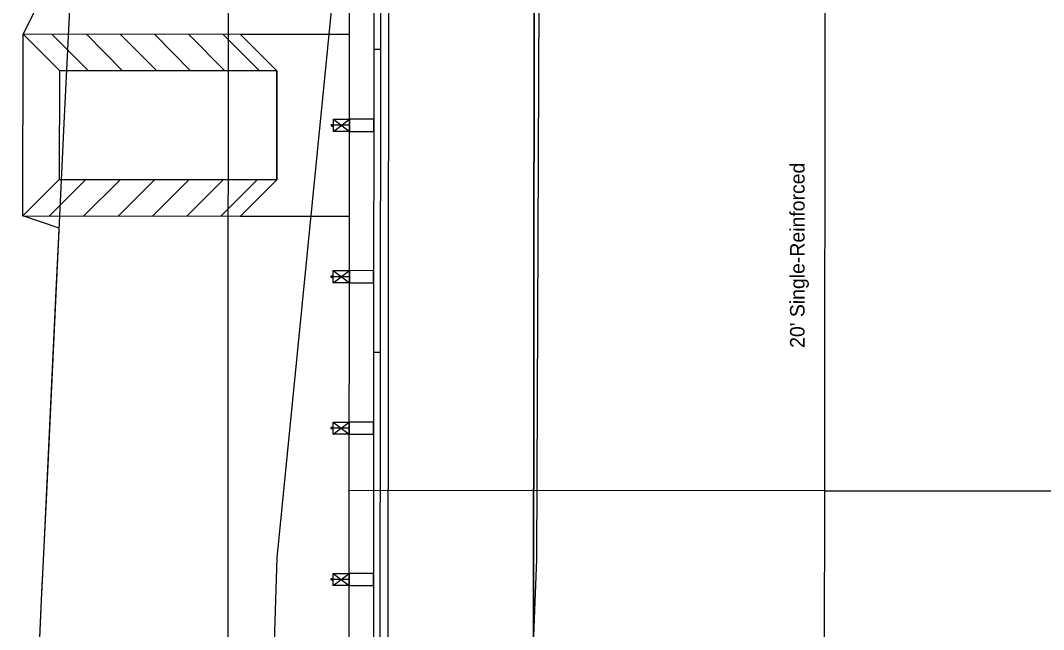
# Model space of a CAD drawing. Extents: x 18543285 to 18543485, y 7434209 to 7435438.
# Drawn here: x 18543351.49 to 18543393.73, y 7434698.69 to 7434723.84 of the extents above; entities that cross this region are included whole.
import ezdxf

# ---------------------------------------------------------------- set-up
doc = ezdxf.new("R2010")
doc.units = 0
for name, color, linetype in [('_CIVIL_CONSTRUCTION', 7, 'Continuous'), ('Contours Major', 7, 'Continuous'), ('Dimensions', 7, 'Continuous'), ('Draft_1', 7, 'Continuous'), ('EdgeUnpaved', 7, 'Continuous'), ('EXT_SNP', 7, 'Continuous'), ('MeshTop', 7, 'Continuous'), ('Terrain', 7, 'Continuous'), ('TL_ForeSlope', 7, 'Continuous'), ('TL_Grading', 7, 'Continuous'), ('TL_GroundIntercept', 7, 'Continuous')]:
    doc.layers.add(name, color=color, linetype=linetype)

# ---------------------------------------------------------------- blocks, each defined once
blk = doc.blocks.new('MGS_Barrier_Transition_TypeD')
at = {"layer": 'TL_Grading'}
for p, q in [((24.167, -0.25), (36.667, -0.25)), ((36.667, -0.52), (36.667, -0.25)), ((24.167, -0.52), (36.667, -0.52))]:
    blk.add_line(p, q, dxfattribs=at)

msp = doc.modelspace()

# ---------------------------------------------------------------- linework, layer by layer
at = {"layer": '_CIVIL_CONSTRUCTION'}
msp.add_line((18543372.717, 7434758.131), (18543372.483, 7434398.131), dxfattribs=at)
at = {"layer": 'Contours Major'}
msp.add_line((18543366.494, 7434414.304), (18543366.721, 7434764.553), dxfattribs=at)
msp.add_lwpolyline([(18543365.016, 7434626.011), (18543365.02, 7434631.761), (18543365.02, 7434632.261), (18543365.024, 7434638.011), (18543365.024, 7434638.511), (18543365.056, 7434688.511), (18543365.06, 7434694.261), (18543365.06, 7434694.761), (18543365.065, 7434700.511), (18543365.064, 7434701.011), (18543365.085, 7434732.261), (18543365.086, 7434734.886), (18543365.101, 7434758.323), (18543365.101, 7434758.823), (18543365.134, 7434759.303)], dxfattribs=at)
at = {"layer": 'Dimensions'}
for p, q in [((18543353.299, 7434719.593), (18543353.536, 7434724.587)), ((18543353.062, 7434714.599), (18543353.299, 7434719.593)), ((18543352.825, 7434709.604), (18543353.062, 7434714.599)), ((18543352.587, 7434704.61), (18543352.825, 7434709.604)), ((18543352.35, 7434699.615), (18543352.587, 7434704.61)), ((18543352.113, 7434694.621), (18543352.35, 7434699.615))]:
    msp.add_line(p, q, dxfattribs=at)
at = {"layer": 'Draft_1'}
msp.add_lwpolyline([(18543384.77, 7434781.083), (18543372.9, 7434787.863), (18543372.96, 7434740.606), (18543372.8, 7434701.585), (18543372.37, 7434691.21), (18543372.62, 7434685.7), (18543372.86, 7434650.748), (18543372.86, 7434601.252), (18543372.78, 7434549.829), (18543372.8, 7434512.681), (18543372.38, 7434462.376), (18543372.39, 7434412.042), (18543372.69, 7434360.71), (18543372.51, 7434311.653), (18543372.28, 7434264.026), (18543372.36, 7434218.914)], dxfattribs=at)
at = {"layer": 'EdgeUnpaved'}
msp.add_lwpolyline([(18543366.95, 7434783.457), (18543367.08, 7434760.542), (18543365.95, 7434740.647), (18543362.08, 7434701.65), (18543360.3, 7434648.83), (18543359.65, 7434601.121), (18543356.68, 7434548.03), (18543360.21, 7434529.205), (18543361.5, 7434513.228), (18543365.09, 7434461.857), (18543364.63, 7434411.718), (18543364.49, 7434411.599), (18543365.08, 7434359.945), (18543365.18, 7434311.057), (18543365.28, 7434264.086), (18543364.89, 7434219.782)], dxfattribs=at)
at = {"layer": 'EXT_SNP'}
msp.add_lwpolyline([(18543366.95, 7434783.457), (18543367.08, 7434760.542), (18543365.95, 7434740.647), (18543362.08, 7434701.65), (18543360.3, 7434648.83), (18543359.65, 7434601.121), (18543356.68, 7434548.03), (18543360.21, 7434529.205), (18543361.5, 7434513.228), (18543365.09, 7434461.857), (18543364.63, 7434411.718), (18543364.49, 7434411.599), (18543365.08, 7434359.945), (18543365.18, 7434311.057), (18543365.28, 7434264.086), (18543364.89, 7434219.782)], dxfattribs=at)
at = {"layer": 'MeshTop'}
msp.add_lwpolyline([(18543360.016, 7434626.014), (18543360.02, 7434631.761), (18543360.02, 7434632.262), (18543360.024, 7434638.011), (18543360.024, 7434638.512), (18543360.056, 7434688.514), (18543360.06, 7434694.261), (18543360.06, 7434694.762), (18543360.065, 7434700.511), (18543360.064, 7434701.011), (18543360.085, 7434732.264), (18543360.086, 7434734.889), (18543360.101, 7434758.323), (18543360.101, 7434758.996), (18543360.135, 7434759.477)], dxfattribs=at)
msp.add_lwpolyline([(18543360.016, 7434626.014), (18543360.02, 7434631.761), (18543360.02, 7434632.262), (18543360.024, 7434638.011), (18543360.024, 7434638.512), (18543360.056, 7434688.514), (18543360.06, 7434694.261), (18543360.06, 7434694.762), (18543360.065, 7434700.511), (18543360.064, 7434701.011), (18543360.085, 7434732.264), (18543360.086, 7434734.889), (18543360.101, 7434758.323), (18543360.101, 7434758.996), (18543360.135, 7434759.477)], dxfattribs=at)
msp.add_lwpolyline([(18543360.016, 7434626.014), (18543360.02, 7434631.761), (18543360.02, 7434632.262), (18543360.024, 7434638.011), (18543360.024, 7434638.512), (18543360.056, 7434688.514), (18543360.06, 7434694.261), (18543360.06, 7434694.762), (18543360.065, 7434700.511), (18543360.064, 7434701.011), (18543360.085, 7434732.264), (18543360.086, 7434734.889), (18543360.101, 7434758.323), (18543360.101, 7434758.996), (18543360.135, 7434759.477)], dxfattribs=at)
at = {"layer": 'TL_ForeSlope'}
for p, q in [((18543372.663, 7434674.434), (18543372.719, 7434761.085)), ((18543372.663, 7434674.434), (18543372.717, 7434758.114)), ((18543384.695, 7434724.426), (18543384.682, 7434704.426)), ((18543384.682, 7434704.426), (18543365.057, 7434704.439)), ((18543384.682, 7434704.426), (18543365.067, 7434704.439)), ((18543384.682, 7434704.426), (18543384.669, 7434684.426)), ((18543384.682, 7434704.426), (18543408.307, 7434704.411)), ((18543384.682, 7434704.426), (18543408.298, 7434704.411))]:
    msp.add_line(p, q, dxfattribs=at)
at = {"layer": 'TL_Grading'}
for p, q in [((18543353.096, 7434721.769), (18543351.597, 7434723.27)), ((18543354.289, 7434721.768), (18543352.792, 7434723.269)), ((18543355.702, 7434721.767), (18543354.212, 7434723.268)), ((18543357.12, 7434721.766), (18543355.618, 7434723.267)), ((18543358.516, 7434721.765), (18543357.037, 7434723.266)), ((18543359.926, 7434721.764), (18543358.447, 7434723.265)), ((18543361.356, 7434721.763), (18543359.865, 7434723.264)), ((18543360.579, 7434723.264), (18543362.08, 7434721.761)), ((18543362.078, 7434721.763), (18543360.579, 7434723.264)), ((18543365.074, 7434715.761), (18543365.079, 7434723.261)), ((18543366.079, 7434722.635), (18543366.071, 7434710.135)), ((18543366.35, 7434722.635), (18543366.079, 7434722.635)), ((18543366.35, 7434722.635), (18543366.342, 7434710.135)), ((18543362.075, 7434717.263), (18543362.078, 7434721.763)), ((18543364.312, 7434719.512), (18543364.305, 7434719.512)), ((18543364.409, 7434719.261), (18543365.076, 7434719.761)), ((18543364.41, 7434719.761), (18543365.076, 7434719.261)), ((18543365.076, 7434719.511), (18543364.41, 7434719.511)), ((18543365.076, 7434719.761), (18543365.076, 7434719.261)), ((18543366.077, 7434719.76), (18543365.076, 7434719.761)), ((18543366.077, 7434719.26), (18543366.077, 7434719.76)), ((18543365.076, 7434719.261), (18543366.077, 7434719.26)), ((18543354.195, 7434717.268), (18543352.694, 7434715.769)), ((18543355.613, 7434717.267), (18543354.112, 7434715.768)), ((18543357.024, 7434717.266), (18543355.523, 7434715.767)), ((18543358.436, 7434717.265), (18543356.935, 7434715.766)), ((18543359.854, 7434717.264), (18543358.353, 7434715.765)), ((18543361.268, 7434717.263), (18543359.767, 7434715.764)), ((18543362.075, 7434717.263), (18543360.574, 7434715.764)), ((18543364.308, 7434713.262), (18543364.301, 7434713.262)), ((18543364.405, 7434713.011), (18543365.072, 7434713.511)), ((18543364.406, 7434713.511), (18543365.072, 7434713.011)), ((18543365.072, 7434713.261), (18543364.406, 7434713.261)), ((18543365.072, 7434713.511), (18543365.072, 7434713.011)), ((18543366.073, 7434713.51), (18543365.072, 7434713.511)), ((18543366.073, 7434713.01), (18543366.073, 7434713.51)), ((18543365.072, 7434713.011), (18543366.073, 7434713.01)), ((18543366.071, 7434710.135), (18543366.063, 7434697.635)), ((18543366.342, 7434710.135), (18543366.071, 7434710.135)), ((18543366.342, 7434710.135), (18543366.071, 7434710.135)), ((18543366.342, 7434710.135), (18543366.334, 7434697.635)), ((18543364.401, 7434706.761), (18543365.068, 7434707.261)), ((18543364.402, 7434707.261), (18543365.068, 7434706.761)), ((18543365.068, 7434707.261), (18543365.068, 7434706.761)), ((18543366.069, 7434707.26), (18543365.068, 7434707.261)), ((18543366.069, 7434706.76), (18543366.069, 7434707.26)), ((18543364.304, 7434707.012), (18543364.297, 7434707.012)), ((18543365.068, 7434707.011), (18543364.402, 7434707.011)), ((18543365.068, 7434706.761), (18543366.069, 7434706.76)), ((18543364.397, 7434700.511), (18543365.064, 7434701.011)), ((18543364.398, 7434701.011), (18543365.064, 7434700.511)), ((18543365.064, 7434701.011), (18543365.064, 7434700.511)), ((18543366.065, 7434701.01), (18543365.064, 7434701.011)), ((18543366.065, 7434700.51), (18543366.065, 7434701.01)), ((18543364.3, 7434700.762), (18543364.293, 7434700.762)), ((18543365.064, 7434700.761), (18543364.397, 7434700.761)), ((18543365.064, 7434700.511), (18543366.065, 7434700.51))]:
    msp.add_line(p, q, dxfattribs=at)
for points in [[(18543362.078, 7434721.763), (18543360.579, 7434723.264), (18543351.597, 7434723.27), (18543353.096, 7434721.769), (18543362.078, 7434721.763)], [(18543362.078, 7434721.763), (18543362.075, 7434717.263), (18543360.574, 7434715.764), (18543365.074, 7434715.761), (18543365.079, 7434723.261), (18543360.579, 7434723.264), (18543362.078, 7434721.763)], [(18543353.096, 7434721.769), (18543353.093, 7434717.269), (18543362.075, 7434717.263), (18543362.078, 7434721.763), (18543353.096, 7434721.769)], [(18543364.367, 7434719.531), (18543364.312, 7434719.531), (18543364.312, 7434719.492), (18543364.367, 7434719.492)], [(18543364.41, 7434719.545), (18543364.367, 7434719.545), (18543364.367, 7434719.478), (18543364.41, 7434719.478)], [(18543351.592, 7434715.77), (18543360.574, 7434715.764), (18543362.075, 7434717.263), (18543353.093, 7434717.269), (18543351.592, 7434715.77)], [(18543364.363, 7434713.281), (18543364.308, 7434713.281), (18543364.308, 7434713.242), (18543364.363, 7434713.242)], [(18543364.406, 7434713.295), (18543364.363, 7434713.295), (18543364.363, 7434713.228), (18543364.406, 7434713.228)], [(18543364.358, 7434707.031), (18543364.304, 7434707.031), (18543364.304, 7434706.992), (18543364.358, 7434706.992)], [(18543364.402, 7434707.045), (18543364.358, 7434707.045), (18543364.358, 7434706.978), (18543364.402, 7434706.978)], [(18543364.354, 7434700.781), (18543364.3, 7434700.781), (18543364.3, 7434700.742), (18543364.354, 7434700.742)], [(18543364.398, 7434700.795), (18543364.354, 7434700.795), (18543364.354, 7434700.728), (18543364.397, 7434700.728)]]:
    msp.add_lwpolyline(points, dxfattribs=at)
for points in [[(18543365.076, 7434719.761), (18543365.076, 7434719.261), (18543364.409, 7434719.261), (18543364.41, 7434719.761)], [(18543365.072, 7434713.511), (18543365.072, 7434713.011), (18543364.405, 7434713.011), (18543364.406, 7434713.511)], [(18543365.068, 7434707.261), (18543365.068, 7434706.761), (18543364.401, 7434706.761), (18543364.402, 7434707.261)], [(18543365.064, 7434701.011), (18543365.064, 7434700.511), (18543364.397, 7434700.511), (18543364.398, 7434701.011)]]:
    msp.add_lwpolyline(points, close=True, dxfattribs=at)
at = {"layer": 'TL_GroundIntercept'}
msp.add_lwpolyline([(18543351.32, 7434677.401), (18543351.49, 7434681.492), (18543351.533, 7434682.401), (18543351.63, 7434684.451), (18543351.771, 7434687.401), (18543351.824, 7434688.52), (18543352.008, 7434692.401), (18543352.096, 7434694.266), (18543352.12, 7434694.769), (18543352.245, 7434697.401), (18543352.393, 7434700.519), (18543352.417, 7434701.019), (18543352.483, 7434702.401), (18543352.72, 7434707.4), (18543352.804, 7434709.175), (18543352.901, 7434711.22), (18543352.929, 7434711.8), (18543352.957, 7434712.4), (18543353.077, 7434714.925), (18543353.093, 7434715.265), (18543351.592, 7434715.77), (18543351.597, 7434723.27), (18543351.597, 7434723.27), (18543353.669, 7434727.4)], dxfattribs=at)

# ---------------------------------------------------------------- block references
at = {"layer": 'Contours Major', "yscale": -0.9999999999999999, "rotation": -90.03723823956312}
msp.add_blockref('MGS_Barrier_Transition_TypeD', (18543365.853, 7434759.302), dxfattribs=at)

# ---------------------------------------------------------------- texts
at = {"layer": 'Terrain'}
msp.add_text("20' Single-Reinforced", height=0.6, rotation=89.9628, dxfattribs=at).set_placement((18543383.863, 7434710.323))

doc.saveas('drawing.dxf')
